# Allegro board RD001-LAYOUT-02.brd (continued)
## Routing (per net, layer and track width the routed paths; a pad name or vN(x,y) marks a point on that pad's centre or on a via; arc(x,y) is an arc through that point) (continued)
HS1_1: length 7.1
  TOP w0.5: v4(173.6,121) 176.8,117.8 176.8,115.53
  TOP w0.72: 176.8,115.53 R224.2
HS1_2: length 6.4
  TOP w0.5: 84.43,121 v4(90.5,121)
  TOP w0.72: R225.2 84.43,121
LGND: length 151.7
  TOP w0.3: v2(230.1,61.55) 229.87,61.22 229.66,60.86 ; v2(244.3,6.5) 244.66,6.5 R208.1 ; 240.04,9.49 240.04,8.71 v2(240,8.3) ; v2(240,3.5) 240.04,3.91 240.04,4.71 ; v2(244.3,9.3) 244.71,9.3 245.14,9 ; R55.1 259.9,10 260.05,9.85 v2(260.05,8.9) ; R70.1 247.7,10.96 v2(247.7,12.1)
  TOP w0.45: 226.95,95.01 226.95,93.09 ; 226.95,92.01 226.95,90.9 v2(228.3,89.55) v2(229.55,89.55) ; v2(229.8,99) 228.97,98.17 C61.1 227.35,97.4 226.95,97 226.95,96.31
  TOP w0.5: 256.04,16.09 256.04,17.41 ; 256.04,8.29 256.04,9.61 ; v2(257,11.2) 257,11.6 256.7,11.9 256.16,11.9 ; v2(235.3,96.55) 235.3,97.1 235.53,97.33 IC6.3 ; 256.04,12.19 256.04,13.61 ; 256.04,14.19 256.04,15.51 ; 256.04,6.39 256.04,7.71 ; 259.31,6.1 259.78,5.82 v2(260.2,5.4) ; v2(256.04,18.65) 256.04,17.99 ; 256.04,10.19 256.04,11.61
  TOP w0.55: 229.66,60.16 229.66,60.86
  TOP w0.72: 256.04,10.19 R51.1 256.04,9.61 ; R180.1 256.04,12.19 ; R180.1 256.16,11.9 ; R180.1 256.04,11.61 ; R197.2 240.04,4.71 ; 256.04,8.29 R53.1 256.04,7.71 ; 256.04,16.09 R181.1 256.04,15.51 ; 245.14,9 R209.1 ; R184.1 259.31,6.1 ; 256.04,17.99 R50.1 256.04,17.41 ; R196.2 240.04,9.49 ; 256.04,14.19 R52.1 256.04,13.61 ; R182.1 256.04,6.39
  TOP w0.92: 226.95,96.31 C88.1 226.95,95.01 ; 226.95,92.01 C89.1 226.95,93.09
  TOP w1: C3.1 292.5,121.5 ; C3.1 291,120 ; C3.1 294,120 ; C5.1 301.5,88.5 ; C5.1 303,90 ; C5.1 301.5,91.5 ; C4.1 301.5,105 ; C4.1 301.5,102 ; C4.1 303,103.5 ; C6.1 268,120 ; C6.1 266.5,121.5 ; C6.1 265,120 ; C2.1 278,120 ; C2.1 279.5,121.5 ; C2.1 281,120
  CONDUCTIVE4 w0.2: v2(237.4,14.1) 237.4,13.7 241.8,9.3 v2(242.8,9.3)
  BOTTOM w0.3: 226.65,42.05 v2(226.65,42.7) ; v2(237.4,14.1) 237.6,14.3 237.6,14.7 231.9,20.4 229,20.4 227.95,19.35 227.04,19.35 ; R22.1 245.24,61.36 v2(245.25,60.95) ; v2(260.2,5.4) 259.25,5.4 ; v2(246.4,17.2) 246.6,17 246.6,16.6 ; R66.1 v2(244.3,9.3) ; v2(240,3.5) 240,2.96 240.04,2.42 ; R45.1 v2(261,16.2) ; v2(260.05,8.9) 260.05,8.35 259.9,8.2 259.36,8.2 ; R25.1 225.26,44.94 v2(225.65,44.8) ; IC10.24 249.34,16.62 v2(249.3,17) ; 257.45,14.44 257.99,14.5 v2(258.4,14.5) 259.06,14.5 R43.1 ; 240.04,7.22 240,7.76 v2(240,8.3) ; v2(247.7,17.2) 247.7,16.45 ; 246.78,16.43 247.53,16.43 ; v2(247.7,12.1) 247.7,11.35 ; v2(230.1,61.55) 230.3,61.75 230.92,61.75 ; v2(257,11.2) 257.52,11.72 257.52,11.99 ; 253.62,17.3 v2(252.9,17.3) ; R64.1 v2(244.3,6.5)
  BOTTOM w0.45: 247.7,16.45 C24.1 247.53,16.43 ; D26.A 228.2,93.75 v2(228.25,93.8) ; 253.68,17.3 253.62,17.3 ; v2(221.6,25.45) R9.1 ; 247.7,11.35 247.7,11.32 ; C100.1 v2(269.5,27.3) 269.51,27.32 269.51,28.27 ; 257.52,12 257.52,11.99 ; 268.11,28.55 268.11,27.31 v2(268.1,27.3) ; 246.78,16.43 C23.1 246.6,16.6
  BOTTOM w0.5: v1(235.1,114.6) 233.6,114.6 233.15,114.15 D27.A ; R21.1 237.59,96.55 v2(235.3,96.55) ; R19.1 235.3,107.64 v1(235.3,106) ; v2(253.7,5.1) 253.7,5.77
  BOTTOM w0.55: D29.A 226.65,42.05 ; IC8.3 269.51,28.27 ; D28.A 230.92,61.75
  BOTTOM w0.72: 253.7,5.77 R54.1 ; 240.04,2.42 R195.2 ; 257.45,14.44 R48.1 ; 240.04,7.22 R194.2 ; 259.36,8.2 R56.1 ; 259.25,5.4 R61.1
  BOTTOM w0.825: IC8.4 268.11,28.55
  BOTTOM w0.92: R185.1 227.04,19.35
  BOTTOM w1: C5.1 303,90 ; C5.1 301.5,88.5 ; C5.1 301.5,91.5 ; C6.1 265,120 ; C6.1 266.5,121.5 ; C6.1 269.5,120 ; C2.1 279.5,121.5 ; C2.1 276.5,120 ; C2.1 281,120 ; C4.1 301.5,105 ; C4.1 301.5,102 ; C4.1 303,103.5 ; C3.1 294,120 ; C3.1 291,120 ; C3.1 292.5,121.5
  vias: v1(227.85,81.85) v1(227.85,79.75) v1(229.95,81.85) v1(229.95,79.75) v1(229.95,77.65) v1(235.05,120.5) v1(235.1,49.45) v1(235.1,46.05) v1(235.3,103.9) v1(235.3,101.8) v1(235.3,59.35) v1(235.3,57.25) v1(235.3,55.15) v1(235.4,73.8) v1(235.4,71.7) v1(235.4,68.7) v1(236.25,122.6) v1(236.35,51.15) v1(236.35,47.75) v1(236.35,44.35) v1(236.7,60.95) v1(237.15,120.5) v1(237.2,114.6) v1(237.4,106) v1(237.4,103.9) v1(237.4,101.8) v1(237.5,73.8) v1(237.5,71.7) v1(237.5,68.7) v1(238.35,122.6) v1(238.8,60.95) v1(239.3,120.5) v1(239.5,108.1) v1(239.5,106) v1(239.5,103.9) v1(239.5,101.8) v1(239.6,73.8) v1(239.6,71.7) v1(240.45,122.6) v1(240.9,60.95) v1(241.7,71.7) v1(242.55,122.6) v1(262,122.5) v1(271,122.5) v1(273,122.5) v1(273,120.5) v1(275,122.5) v1(275.1,28.6) v1(275.1,25.6) v1(275.1,22.6) v1(275.1,19.6) v1(275.1,16.6) v1(275.1,13.6) v1(275.1,10.6) v1(275.1,7.6) v1(277.1,27.1) v1(277.1,24.1) v1(277.1,21.1) v1(277.1,18.1) v1(277.1,15.1) v1(277.1,12.1) v1(277.1,9.1) v1(279.1,34.4) v1(279.1,31.4) v1(279.1,13.6) v1(279.1,10.6) v1(279.1,7.6) v1(281.1,32.9) v1(281.1,29.9) v1(281.1,12.1) v1(281.1,9.1) v1(283.1,34.4) v1(283.1,31.4) v1(283.1,13.6) v1(283.1,10.6) v1(283.1,7.6) v1(284,122.5) v1(285.1,32.9) v1(285.1,29.9) v1(285.1,12.1) v1(285.1,9.1) v1(286,122.5) v1(286,120.5) v1(287.1,34.4) v1(287.1,31.4) v1(287.1,28.4) v1(287.1,13.6) v1(287.1,10.6) v1(287.1,7.6) v1(288,122.5) v1(289.1,32.9) v1(289.1,29.9) v1(289.1,12.1) v1(289.1,9.1) v1(291.1,31.4) v1(291.1,28.4) v1(291.1,13.6) v1(291.1,10.6) v1(291.1,7.6) v1(293.1,32.9) v1(293.1,29.9) v1(293.1,12.1) v1(293.1,9.1) v1(295.1,34.4) v1(295.1,31.4) v1(295.1,28.4) v1(295.1,13.6) v1(295.1,10.6) v1(295.1,7.6) v1(297.1,32.9) v1(297.1,29.9) v1(297.1,12.1) v1(297.1,9.1) v1(297.5,122.5) v1(299,116.4) v1(299.1,34.4) v1(299.1,31.4) v1(299.1,13.6) v1(299.6,113.12) v1(299.9,110.8) v1(299.9,83.5) v1(299.9,81.5) v1(301.1,32.9) v1(301.1,29.9) v1(301.1,26.9) v1(301.1,23.9) v1(301.1,20.9) v1(301.1,17.9) v1(301.1,14.9) v1(301.92,116.4) v1(302,110) v1(302,96.5) v1(302,83.5) v1(302,81.5) v1(303.1,31.4) v1(303.1,28.4) v1(303.1,25.4) v1(303.1,22.4) v1(303.1,19.4) v1(303.1,16.4) v1(304,110) v1(304,108) v1(304,98.5) v1(304,96.5) v1(304,94.5) v1(304,85.5) v1(304,83.5) v1(304,81.5) v2(233.35,52.8) v2(234.6,52.8) v2(304.5,72) v2(304.5,66.6) v2(304.5,62) v2(304.5,57) v2(304.5,52) v2(304.5,47) v2(304.5,43.8) v2(304.5,40.55) v3(281.5,24.5) v3(281.5,18) v3(297.5,24.5)
OUTA1: length 162.8
  TOP w0.3: v2(140.6,107.5) 141.06,107.5 R111.1
  CONDUCTIVE3 w0.2: v2(217.7,6.1) 217,6.8 217,7.85 215.8,9.05 213,9.05 210.25,11.8 199.6,11.8 194.11,17.29 191.61,17.29 178.55,30.35 178.55,53.15 168.68,63.02 156.75,63.02 154.57,65.2 154.57,69.4 150.57,73.4 143.65,73.4 139,78.05 139,89.25 142.65,92.9 142.65,106.55 141.7,107.5 v2(140.6,107.5)
  BOTTOM w0.3: 220.03,6.88 220.03,6.36 220.06,5.82 ; v2(217.7,6.1) 217.7,5.75 218.1,5.35 219.36,5.35 219.84,5.6
  BOTTOM w0.6: IC21.4 220.03,6.88
  BOTTOM w0.72: 219.84,5.6 R187.2 220.06,5.82
OUTA2: length 12.9
  BOTTOM w0.3: 240.26,9.6 240.9,9.6 241.45,10.15 241.45,12.65 243.57,14.78 248.58,14.78
  BOTTOM w0.4: 248.58,14.78 IC10.22
  BOTTOM w0.72: R149.2 240.26,9.6
OUTB1: length 163.2
  TOP w0.3: v2(140.6,104.1) 141.01,104.1 141.5,103.9
  TOP w0.72: 141.5,103.9 R110.1
  CONDUCTIVE3 w0.2: v2(140.6,104.1) 141.65,104.1 142.25,103.5 142.25,93.1 138.6,89.45 138.6,77.88 143.48,73 150.4,73 154.18,69.22 154.18,65.03 156.57,62.62 168.47,62.62 178.15,52.95 178.15,30.15 191.41,16.89 193.91,16.89 199.4,11.4 210.05,11.4 212.95,8.5 215.75,8.5 216.6,7.65 216.6,3.15 v2(217.7,2.05)
  BOTTOM w0.3: 219.84,1.4 219.36,1.15 218.35,1.15 217.84,1.66 v2(217.7,2.05) ; 220.06,1.62 220.03,2.16 220.03,2.67
  BOTTOM w0.6: IC22.4 220.03,2.67
  BOTTOM w0.72: 219.84,1.4 R189.2 220.06,1.62
OUTB2: length 17.1
  BOTTOM w0.3: 240.26,4.8 241.2,4.8 242.05,5.65 242.05,12.4 243.78,14.12 248.58,14.12
  BOTTOM w0.4: IC10.21 248.58,14.12
  BOTTOM w0.72: 240.26,4.8 R150.2
OUTC1: length 102.2
  TOP w0.3: v2(163.38,60.25) 162.9,59.77 159.06,59.77 157.83,58.55 156.61,58.55 R113.1 ; 220.14,9.7 218.2,9.7 v2(215.9,7.4) ; R191.2 219.94,9.28 219.94,8.55
  TOP w0.6: 219.94,8.55 IC23.4
  TOP w0.72: 220.14,9.7 R191.2
  CONDUCTIVE3 w0.2: v2(215.9,7.4) 213.45,7.4 209.85,11 199.2,11 193.71,16.49 191.21,16.49 177.75,29.95 177.75,50.8 168.7,59.85 163.78,59.85 v2(163.38,60.25)
OUTC2: length 18.6
  TOP w0.3: 240.26,7 240.7,7 241.2,7.5 241.2,12.5 242.5,13.8 250.8,13.8 v2(251,14)
  TOP w0.72: 240.26,7 R151.2
  BOTTOM w0.3: v2(251,14) 250.67,13.75 250.4,13.47 249.93,13.47
  BOTTOM w0.4: IC10.20 249.93,13.47
OUTD1: length 102.3
  TOP w0.3: 220.29,5.5 219.4,5.5 219.25,5.35 v2(215.9,5.35) ; v2(162.88,61.4) 162.88,60.83 162.43,60.38 158.81,60.38 157.79,59.36 157.42,59.36 ; R193.2 219.94,5.08 219.94,4.35
  TOP w0.6: 219.94,4.35 IC24.4
  TOP w0.72: R193.2 220.29,5.5 ; 157.42,59.36 R112.1
  CONDUCTIVE3 w0.2: v2(215.9,5.35) 214.9,5.35 209.65,10.6 199,10.6 193.51,16.09 191.01,16.09 177.35,29.75 177.35,50.45 168.35,59.45 163.24,59.45 162.72,59.98 162.72,60.84 162.88,61 v2(162.88,61.4)
OUTD2: length 22.4
  TOP w0.3: 240.26,2.2 240.75,2.2 242.05,3.5 242.05,12.45 242.6,13 v2(251,13)
  TOP w0.72: R152.2 240.26,2.2
  BOTTOM w0.3: v2(251,13) 250.63,12.82 249.97,12.82
  BOTTOM w0.4: IC10.19 249.97,12.82
OUTE: length 129.2
  TOP w0.3: 230.94,59.34 230.94,58.74 231.08,58.6 v2(231.7,58.6) ; v2(232.1,43.75) 232.1,40.6 231.5,40 230.2,40 ; 234.8,92.65 234.8,94.75 v2(235.25,95.2) 235.38,95.59 235.67,95.88 236.03,96.06
  TOP w0.55: 230.94,59.34 IC7.2 ; IC6.2 236.03,96.06
  TOP w2.1: 230.2,40 TP25.1 ; 234.8,92.65 TP23.1
  CONDUCTIVE4 w0.2: v2(251,12) 247.9,15.1 242.9,15.1 239.6,18.4 232.05,18.4 225.65,24.8 225.65,37.8 231.6,43.75 v2(232.1,43.75) 232.8,44.45 232.8,45.3 230.75,47.35 230.75,57.65 v2(231.7,58.6) 231.05,59.25 229.45,59.25 228.25,60.45 228.25,76.1 225.25,79.1 225.25,80.55 235.25,90.55 v2(235.25,95.2)
  BOTTOM w0.3: 250.01,12.18 250.63,12.18 v2(251,12)
  BOTTOM w0.4: IC10.18 250.01,12.18
OUTF: length 141.5
  TOP w0.3: 236.16,98.74 235.14,98.74 234.2,97.8 v2(234.2,95.9) ; 230.2,44.7 231.68,45 v2(232.1,45) ; v2(229.3,58.6) 228.56,58.6 228.26,58.9 228.26,59.52 ; v2(222.6,97.6) 222.6,99.4 222.1,99.9 220.8,99.9
  TOP w0.825: 228.26,59.52 IC7.4 ; IC6.4 236.16,98.74
  TOP w2.1: 230.2,44.7 TP26.1 ; 220.8,99.9 TP24.1
  CONDUCTIVE4 w0.2: v2(251,10.75) 247.05,14.7 242.7,14.7 239.4,18 231.85,18 225.25,24.6 225.25,38 231.25,44 231.25,44.15 v2(232.1,45) 232.1,45.4 230.35,47.15 230.35,57.55 v2(229.3,58.6) 227.85,60.05 227.85,75.9 224.85,78.9 224.85,80.75 234.2,90.1 v2(234.2,95.9) 233.74,95.75 231.95,95.75 230.1,97.6 v2(222.6,97.6)
  BOTTOM w0.3: v2(251,10.75) 250.81,11.12 250.4,11.53 249.93,11.53
  BOTTOM w0.4: IC10.17 249.93,11.53
PFC_OUT: length 289.9
  TOP w1: v2(186,6.25) 184.65,4.9 184.65,4.88 184.1,3.4
  TOP w2.1: 184.1,3.4 TP44.1
  CONDUCTIVE4 w5: C7.2 139.1,27.4 133.8,32.7 121.22,32.7 101.3,52.62 101.3,71.68 98.95,74.03 98.95,112.6 99.7,113.35
  BOTTOM w0: C1.2 178.9,21.4 179.8,20.5 R178.2
  BOTTOM w0.3: 172.14,14.72 172.14,17.24 175,20.1 C1.2
  BOTTOM w0.5: 189,20.68 189,14.45 185.25,10.7 185.25,7 v2(186,6.25)
  BOTTOM w0.72: R92.2 172.14,14.72
  BOTTOM w3: 162.15,28.6 162.15,31.4 ; 162.15,28.6 159.35,28.6 ; 162.15,28.6 164.95,28.6 ; 162.15,31.4 161.5,32.05 161.5,45.52 166.38,50.4 D2.C 166.38,54.7 ; 162.15,31.4 159.35,28.6 ; 162.15,31.4 164.95,28.6 ; 159.35,28.6 156,28.6 148.8,21.4 C7.2 136.2,24.3 136.2,45.85 135.18,46.87 D1.C 135.18,54.7 ; T4.2 189,21.35 ; 189,21.35 189,20.68 ; 189,21.35 177.25,21.35 C1.2 177.2,23.33 171.93,28.6 164.95,28.6
PFC_VIN: length 8.8
  TOP w0.5: D9.C 124.58,117.05 v2(125.05,117.05) v2(126.3,117.05)
  TOP w1: D9.C D8.C
  BOTTOM w0.5: v2(126.3,117.05) v2(125.05,117.05) 124.61,117.05 R95.2
PN: length 393.4
  TOP w0.3: R191.1 221.64,9.22 222.06,8.8 IC23.3 ; v2(218.7,4.6) 218.6,4.24 218.6,3.9 ; v2(161.6,5.2) 161.1,5.7 R176.1 ; 227.75,4.89 227.8,5.49 v2(227.8,5.9) 227.12,5.9 226.9,5.67 226.47,5.67 ; 158.83,62.52 158.83,62.12 159.12,61.83 161.19,61.83 ; 161.37,62 161.19,61.83 ; 161.37,62 161.37,61.83 ; 161.37,62 161.37,62.52 ; 161.19,61.83 161.37,61.83 ; 218.6,8 v2(218.6,8.9) ; 88.8,73.53 v2(88.8,72.8) ; Q4.S 159.9,76.55 161.25,75.2 163.25,75.2 164.05,74.4 164.05,73.94 ; 161.37,61.83 161.7,61.49 v2(161.82,61.1) ; 164.24,73.25 170.51,73.25 R33.1 ; R175.1 155.21,6.5 v2(154.8,6.45) ; v2(225.5,1.95) 225.5,1.27 225.7,1.07 226.12,1.07 ; 221.76,9.7 222.19,10 v2(222.6,10) ; v2(224.7,10.05) 226.95,10.05 227,10 227.41,9.57 ; R71.1 v2(155.7,42.9) ; 126.58,49.1 v2(127.8,49.1)
  TOP w0.4: v2(152.4,13.1) 153.39,13.1 154.14,12.35 154.14,11.65 ; 202.4,15.72 v2(202.4,16.5) ; 85.2,73.89 v2(85.2,72.5)
  TOP w0.45: C35.1 151.2,41.3 150.9,41.6 v2(150.3,41.6) ; C62.1 v2(147.9,45.6) ; C57.1 153.04,65 153.04,66.99 v2(153.5,67.45) ; v2(144.7,43.8) 143.74,43.8 143.34,43.4 143.34,42.99 ; v2(167.3,39.2) 167.16,39.06 164.37,39.06 ; 226.47,5.67 C73.1 ; C97.1 218.6,8 ; 143.34,41.37 143.34,40.4 ; 143.34,40.4 C81.1 ; 143.34,40.4 C80.1 ; C70.1 88.8,73.53 ; 226.12,1.07 C74.1 ; 218.6,3.9 C98.1 ; v2(130.4,43.6) 133.18,43.6
  TOP w0.5: v2(172.64,91.2) 172.68,91.24 R223.1 ; 145.03,103.83 145.03,100 ; 145.03,103.83 IC5.5 ; 145.03,103.83 145.03,106.1 145.3,106.37 IC5.3 ; R225.1 82.86,121.92 v2(82.87,121.93) ; v2(150.3,41.6) 149.57,41.6 ; v2(140.6,105.1) 140.8,105.3 C53.1 ; v2(120.4,44.8) 120.4,42.66 119.2,41.46 117.59,41.46 ; 221.76,5.5 222.3,5.5 v2(222.6,5.2) 222.6,4.68 IC24.3 ; v2(150.3,43.9) 149.57,43.9 ; v2(176.8,113.07) R224.1 ; 129.68,62.56 130.84,62.56 v2(130.9,62.5) ; C54.1 v2(140.6,108.7) ; 154.14,11.11 154.14,9.79
  TOP w0.55: IC4.3 158.83,62.52 ; 143.34,42.99 143.34,41.37 ; 164.05,73.94 D25.A 164.24,73.25 ; IC4.5 161.37,62.52
  TOP w0.7: D50.C 85.2,73.89
  TOP w0.72: 164.37,39.06 R221.1 ; 154.14,11.11 R174.1 154.14,11.65 ; R73.1 126.58,49.1 ; 154.14,9.79 R198.1 ; R220.1 129.68,62.56 ; 117.59,41.46 R222.1 ; 221.76,9.7 R191.1 ; 221.76,5.5 R193.1
  TOP w0.8: 227.75,4.89 IC16.4 ; 227.41,9.57 IC15.4
  TOP w0.92: 149.57,41.6 C83.1 ; 149.57,43.9 C82.1
  CONDUCTIVE3 w0.2: v2(105.6,76.9) 106.7,75.8 121.4,75.8 122.75,74.45 122.75,58.5 124.6,56.65 124.6,45.3 132.28,37.62 149.05,37.62 152.6,34.08 152.6,20.6 158.9,14.3 158.9,3.74 v2(158.7,3.3) ; v2(161.6,3.95) 162.7,5.05 162.7,15.63 156.2,22.13 156.2,32.4 149.2,39.4 142.3,39.4 131.9,49.8 128.8,49.8 126.45,52.15 126.45,73.94 v2(126.6,74.4)
  BOTTOM w0.3: C48.1 146.08,9.29 144.7,9.29 ; 157.86,3 158.29,3.3 v2(158.7,3.3) 159.47,2.52 C76.1 ; 160.64,7.04 160.64,5.96 ; 161.99,61.88 161.99,61.34 v2(161.82,61.1) ; 151,7.83 151.47,7.83 v2(151.8,7.5) ; 148.56,7.42 148.9,7.42 149.3,7.83 ; 160.64,7.43 160.64,8.15 C38.1 ; 147.08,3.24 146.46,3.24 v2(146.3,3.4) ; 159.48,11.82 160.15,11.82 160.64,12.32 160.64,14.48 161,14.84 R90.1 ; 149.92,7.83 149.3,7.83 ; 149.3,7.83 148.75,8.38 148.41,8.38 ; 150.56,2.12 150.3,2.59 v2(150.3,3.2) 151.03,3.2 ; C36.1 105.08,76.38 v2(105.6,76.9) 105.12,77.38 103.81,77.38 103.54,77.65 103.54,78.32 ; R8.1 125.2,77.7 125.6,77.3 125.6,75.4 v2(126.6,74.4) 126.08,73.88 C34.1 ; v2(227.8,5.9) 227.75,6.31 IC13.4 ; 147.42,3.24 147.96,3.2 148.3,3.2 ; 148.4,4.11 148.4,3.7 148.47,3.38 ; v2(157.6,9.8) 157.6,10.7 158.72,11.82 159.3,11.82 ; C47.1 148.34,7.42 147.58,8.18 146.98,8.75 ; 157.64,2.84 157.64,1.76
  BOTTOM w0.4: 151,7.83 IC3.16 149.92,7.83 ; 157.45,13.94 158.38,13.94 158.5,13.82 ; R93.1 152.4,13.91 v2(152.4,13.1) 152.81,13.14 C40.1
  BOTTOM w0.45: 160.72,4.5 161.28,3.95 v2(161.6,3.95) ; 148.41,8.38 C49.1 ; 148.56,7.42 C47.1 ; C71.1 224.75,10.1 v2(224.7,10.05) ; C72.1 v2(224.7,5.6) ; C45.1 151.03,3.2 ; 148.47,3.38 C43.1 148.3,3.2 ; C42.1 148.4,4.11 ; C96.1 v2(218.7,2.05) ; 159.48,11.82 159.3,11.82 ; C95.1 v2(218.7,6.1)
  BOTTOM w0.5: v2(225.5,1.95) 226.67,1.95 227.2,2.23 ; 165.99,117.3 166.3,117.3 ; 165.99,117.3 159.26,117.3 R29.1 ; 165.99,117.3 166.3,117.61 ; 166.3,117.3 166.3,117.61 ; 166.3,117.3 166.61,117.3 ; R101.1 161.13,5.57 161.5,5.2 v2(161.6,5.2) 162.34,5.2 R2.1 ; 166.3,117.61 166.61,117.3 ; 166.3,117.61 Q6.S ; 166.61,117.3 168.4,117.3 169.05,116.65 D22.A ; 157.2,14.23 157.2,15.65 156.45,16.4 154.05,16.4 v2(153.9,16.25) ; 151.59,13.14 152.36,13.14 v2(152.4,13.1) ; 221.63,1.4 222.4,1.4 v2(222.95,1.95) 222.95,2.15 222.35,2.75 IC22.3 ; 151.01,13.14 149.69,13.14 ; R187.1 221.74,5.2 v2(222.6,5.2) 222.6,6.62 IC21.3
  BOTTOM w0.72: 221.63,1.4 R189.1 ; 160.64,7.43 R102.1 160.64,7.04 ; 147.42,3.24 R98.1 147.08,3.24 ; 157.64,1.76 R96.1 ; 157.2,14.23 R104.1 157.45,13.94 ; 150.56,2.12 R99.1 ; 151.01,13.14 R103.1 151.59,13.14 ; 149.69,13.14 R100.1 ; 157.64,2.84 C77.1 157.86,3 ; 161.99,61.88 C56.1 ; 160.64,5.96 R101.1
  BOTTOM w0.8: 227.2,2.23 IC14.4
  BOTTOM w0.895: 103.54,78.32 R7.1
  BOTTOM w1.1: 146.98,8.75 C48.1
  BOTTOM w1.2: 144.7,9.29 D49.A
  BOTTOM w1.4: TP45.1 178,2.1 R179.1
  vias: v2(125.15,41.1) v2(126.4,41.1) v2(141.1,101) v2(141.1,99.7) v2(141.1,98.4) v2(142.75,90.05) v2(142.75,88.8) v2(155.9,104.1) v2(155.9,102.8) v2(164.18,61.27) v2(166.1,61.85) v2(166.1,60.6) v2(203.7,12.55) v2(204.95,12.55) v2(210.85,6) v2(210.85,4.75) v2(212.1,6) v2(212.1,4.75)
SIG1: length 95.4
  BOTTOM w0: L11.2 51.9,32.2
  BOTTOM w0.8: R79.2 55.74,27.56 L11.2
  BOTTOM w1.5: C78.2 F1.2
  BOTTOM w5: F1.2 49.5,41.24 44.75,36.49 44.75,22.2 RV1.1 44.2,22.2 C30.2 39.5,14.2 42.2,11.5 45,11.5 51.9,18.4 51.9,32.2
SIG2: length 77.9
  BOTTOM w0.15: C79.2 37,5 C30.1
  BOTTOM w0.8: L11.3 55.74,12.84 R80.1
  BOTTOM w5: 49.8,5.6 48.2,4 32.95,4 C79.2 31.95,20.8 35.95,24.8 ; CN1.3 24.8,26.2 34.6,26.2
SIG6: length 246.3
  TOP w0.15: C65.1 73.3,87.75 ; L12.4 111.95,8.2 C63.2 ; 117.9,94.5 L2.1
  TOP w1: 117.2,121.2 121.08,117.33 D9.A
  TOP w5: 109.05,9.75 111.9,12.6 ; 109.05,9.75 111.9,9.75 111.9,12.6 ; 109.05,9.75 L12.4 ; 111.9,12.6 111.9,26.8 114.15,29.05 114.15,35.26 109.85,39.56 109.85,46.47 99.25,57.07 99.25,72.5 88.34,83.41 77.64,83.41 73.3,87.75 ; 117.9,94.5 117.9,106.5 112.4,112 81.75,112 C33.1
  BOTTOM w0.15: 73.66,87.63 73.3,87.99 C65.1 ; L2.1 117.9,94.5
  BOTTOM w5: C33.1 69.3,109.85 69.3,92.75 C65.1 ; 117.2,121.2 117.2,109.9 117.9,109.2 117.9,94.5
SIG8: length 121.5
  TOP w1: D8.A 119.28,112.9 113.38,118.8 112.1,118.8 109.7,121.2
  TOP w5: C33.2 89.05,94.65 L1.1 ; C65.2 73.3,62.3 76.1,59.5 84.4,59.5 86.45,57.45 86.45,56.3
  BOTTOM w5: L1.1 97.6,94.5 109.3,106.2 109.3,121.2 ; 77.6,95.65 80.8,92.45 80.8,83 73.3,75.5 C65.2
SIG9: length 4.6
  BOTTOM w0.5: IC1.2 60.47,24.2 R79.1 61.73,24.2 IC1.3
SIG10: length 4.6
  BOTTOM w0.5: IC1.6 61.73,16.2 R80.2 60.47,16.2 IC1.7
SIG11: length 50.3
  BOTTOM w3: 142.1,68.38 144.31,68.38 152.89,59.79 156.01,59.79 161.3,54.5 D2.A
  BOTTOM w5: 141.7,69.97 141.7,70.98 135.57,77.11 135.57,91.17 136.55,92.15
SIG12: length 40.7
  BOTTOM w0.15: 110.2,94.5 L1.2
  BOTTOM w3: 127.8,57 126.2,58.6 126.2,63.55 121.3,68.45
  BOTTOM w5: 119.2,72.7 113.28,78.62 113.28,87.58 110.2,90.65 110.2,94.5
SIG15: length 9.9
  BOTTOM w0.3: 129.26,74.8 129.61,74.39 T2.1 ; 129.04,75.02 129,75.56 129,76.28
  BOTTOM w0.55: D12.A 129,76.28
  BOTTOM w0.72: 129.04,75.02 R81.2 129.26,74.8
SIG16: length 1.8
  BOTTOM w0.3: 127.76,74.74 127.76,73.96 127.4,73.6 127.06,73.6
  BOTTOM w0.45: 127.06,73.6 C34.2
  BOTTOM w0.72: R81.1 127.76,74.74
SIG18: length 12.7
  BOTTOM w0: T2.3 142.37,62.45 142.45,62.45
  BOTTOM w3: 142.1,63.23 142.45,62.88 142.45,62.45 148.25,56.65 Q2.D
SIG20: length 10.7
  BOTTOM w0.3: R85.2 108.9,74.8 111.1,72.6 T3.1 ; 108.04,75.02 108,75.56 108,77.78
  BOTTOM w0.55: D13.A 108,77.78
  BOTTOM w0.72: 108.04,75.02 R85.2
SIG21: length 2
  BOTTOM w0.3: R85.1 106.22,74.8 105.92,75.1 105.92,75.92
  BOTTOM w0.45: C36.2 105.92,75.92
SIG23: length 6.4
  TOP w0.3: 160.47,44.83 159.59,44.8 158.9,44.8 ; 158.65,44.41 158.65,43.61 R71.2 ; 158.65,46.46 158.65,45.19
  TOP w0.92: R108.2 158.65,44.41 ; R108.2 158.65,45.19 ; R108.2 158.9,44.8 ; R72.2 158.65,46.46
  TOP w1.17: 160.47,44.83 FB1.1
SIG24: length 4.5
  TOP w0.3: 151.38,39.98 151.64,39.76 152.5,39.76 ; 153.74,39.76 152.66,39.76 ; 153.93,38.19 153.93,39 153.9,39.54
  TOP w0.45: 151.38,39.98 C35.2
  TOP w0.55: D31.A 153.93,38.19
  TOP w0.72: 153.74,39.76 R172.2 153.9,39.54 ; 152.66,39.76 R82.2 152.5,39.76
SIG25: length 4.4
  TOP w0.3: 133.57,42.09 133.57,42.6 134.03,43.05 134.03,43.49 ; 135.16,43.77 135.1,44.31 135.1,44.85 ; 134.2,43.6 135.08,43.6
  TOP w0.45: 134.2,43.6 C37.2 134.03,43.49
  TOP w0.55: 133.57,42.09 D33.A
  TOP w0.72: 135.16,43.77 R173.2 135.08,43.6 ; R86.2 135.1,44.85
SIG27: length 6.4
  TOP w0.3: 122.75,44.83 123.62,44.9 124.31,44.9 ; 124.45,47.7 124.45,48.39 R73.2 ; 124.45,46.56 124.45,45.29
  TOP w0.92: 124.45,46.56 R109.2 124.45,47.7 ; 124.45,45.29 R74.2 124.31,44.9
  TOP w1.17: 122.75,44.83 FB2.1
SIG30: length 16.2
  TOP w0.3: 137.91,45.62 136.78,45.62 136.16,46.24 135.32,46.24 ; R86.1 134.14,47.2 131.33,47.2 ; 138.29,45.62 141.82,45.62 142.06,45.87 142.06,46.44 ; D38.A 131.62,45.48 130.68,46.42 D39.C
  TOP w0.55: 138.29,45.62 D32.C 137.91,45.62 ; IC2.7 142.06,46.44
  TOP w0.72: 135.32,46.24 R86.1
  TOP w1.1: 131.33,47.2 D39.C
SIG39: length 6.8
  BOTTOM w0.3: R89.2 163,13.34 164.16,14.5 168.14,14.5
  BOTTOM w0.72: R91.1 168.14,14.5
SIG40: length 1.2
  BOTTOM w0.3: 170.79,14.5 169.71,14.5
  BOTTOM w0.72: R92.1 170.79,14.5 ; 169.71,14.5 R91.2
SIG43: length 3.5
  BOTTOM w0.3: C45.2 151.95,3.23 152.82,3.23 ; 151.93,3.38 151.93,4 151.45,4.47 150.91,4.47
  BOTTOM w0.45: 151.93,3.38 C45.2 ; C46.2 152.82,3.23
  BOTTOM w0.6: IC3.11 150.91,4.47
SIG44: length 1.4
  BOTTOM w0.3: C46.1 152.53,1.9 151.99,1.9
  BOTTOM w0.72: 151.99,1.9 R99.2
SIG45: length 4.1
  BOTTOM w0.3: 149.32,3.02 149.32,2.27 ; 149.94,5.22 149.62,5.22 149.32,4.92 149.32,3.38
  BOTTOM w0.4: IC3.12 149.94,5.22
  BOTTOM w0.45: 149.32,2.27 149.32,2.1 ; 149.32,3.38 149.32,3.02
SIG46: length 1.2
  BOTTOM w0.3: 148.3,2.1 147.96,2.1 147.45,1.96
  BOTTOM w0.45: C44.1 148.3,2.1
  BOTTOM w0.72: 147.45,1.96 R98.2
SIG47: length 7.2
  BOTTOM w0.3: 155.3,12.96 154.87,12.52 154.21,11.86 153.41,11.86 ; 153.4,11.64 153.4,10.93 155.2,9.12 155.75,9.12
  BOTTOM w0.4: 156.32,9.12 155.75,9.12
  BOTTOM w0.72: 153.41,11.86 C40.2 153.4,11.64
  BOTTOM w0.83: 155.3,12.96 C41.2
SIG48: length 2.9
  BOTTOM w0.4: 154.77,14.8 154.15,14.8 153.31,15.64 152.77,15.64
  BOTTOM w0.72: 152.77,15.64 R93.2
  BOTTOM w0.83: C41.1 154.77,14.8
SIG49: length 23.9
  TOP w0.3: v2(154.8,8.5) 158.65,8.5 160.6,6.55 161.55,6.55 162.85,5.25 162.85,3.16 163.05,1.6
  TOP w2.1: 163.05,1.6 TP8.1
  BOTTOM w0.3: 161.37,11.06 160.4,11.06 160.31,10.97 159.45,10.97 ; v2(154.8,8.5) 155.21,8.47 155.63,8.47 ; 156.85,8.47 157.38,8.47 159.3,10.4 159.3,10.8 ; 161.72,11.06 162.88,11.06
  BOTTOM w0.4: 155.63,8.47 156.85,8.47
  BOTTOM w0.45: 159.3,10.8 C39.2 159.45,10.97
  BOTTOM w0.72: 161.72,11.06 R227.2 161.37,11.06 ; 162.88,11.06 R89.1
SIG50: length 2.1
  BOTTOM w0.3: 149.78,9.12 149.2,9.12 149.1,9.22 148.41,9.22
  BOTTOM w0.4: 149.78,9.12 IC3.18
  BOTTOM w0.45: 148.4,9.22 148.41,9.22
SIG51: length 5
  BOTTOM w0.3: 156.53,10.53 158.5,12.5 158.5,12.84 ; 158.59,12.97 159.22,12.97 R171.1
  BOTTOM w0.45: 158.59,12.97 C50.2 158.5,12.84
  BOTTOM w0.6: 156.32,10.53 156.53,10.53
SIG52: length 7.2
  TOP w0.3: 152.64,9.5 149.8,9.5 v2(149.2,10.1)
  TOP w0.72: R198.2 152.64,9.5
  BOTTOM w0.3: 149.85,9.78 149.43,9.78 149.2,10 v2(149.2,10.1) 149.2,11.2 149.4,11.7
  BOTTOM w0.4: IC3.19 149.85,9.78
  BOTTOM w0.72: R100.2 149.4,11.7
SIG53: length 4.6
  TOP w0.3: R176.2 158.76,6.2 v2(158.2,6.2)
  BOTTOM w0.3: R101.2 158.96,6.2 v2(158.2,6.2) 157.88,6.53 157.02,6.53
  BOTTOM w0.4: 156.32,6.53 157.02,6.53
SIG54: length 4.5
  TOP w0.3: R175.2 157.74,7.2 v2(158.2,7.2)
  BOTTOM w0.3: 157.02,7.17 157.79,7.17 v2(158.2,7.2) 159.15,7.2
  BOTTOM w0.4: 156.32,7.17 157.02,7.17
  BOTTOM w0.72: 159.15,7.2 R102.2
SIG55: length 4.1
  TOP w0.3: v2(151.8,10.6) 152.37,11.17 R174.2
  BOTTOM w0.3: 150.91,10.53 151.39,10.53 v2(151.8,10.6) 151.8,11.36 R103.2
  BOTTOM w0.6: IC3.20 150.91,10.53
SIG56: length 5.3
  BOTTOM w0.3: 157.2,12.59 157.2,12.15 156.55,11.5 155.74,11.5 155,10.76 155,10.2 155.43,9.78 155.65,9.78
  BOTTOM w0.4: 156.32,9.78 155.65,9.78
  BOTTOM w0.72: 157.2,12.59 R104.2
SIG60: length 1.2
  BOTTOM w0.5: 123.9,114.99 123.9,113.91
  BOTTOM w0.72: R95.1 123.9,114.99 ; 123.9,113.91 R94.2
SIG61: length 199
  CONDUCTIVE3 w1: v2(166.35,3.4) 166.35,2.25 165.3,1.2 144.5,1.2 113,32.7 113,45.35 103.7,54.65 103.7,72.2 85.45,90.45 85.45,102.45 94.1,111.1 v2(123.9,111.1)
  BOTTOM w0.3: 163.4,8.06 164.26,8.06 166.35,5.97 v2(166.35,3.4)
  BOTTOM w0.5: 123.9,112.37 v2(123.9,111.1)
  BOTTOM w0.72: R94.1 123.9,112.37 ; R1.2 163.4,8.06
SIG62: length 18.1
  TOP w0.3: v2(154.8,7.45) 154.25,7.45 154,7.2 154,5.7 154.7,5 155.75,5 157.8,2.95 TP7.1
  BOTTOM w0.3: 162.12,9.34 163.28,9.34 ; 160.48,9.34 161.77,9.34 ; 156.98,7.83 157.75,7.83 159.26,9.34 160.12,9.34 ; v2(154.8,7.45) 155.18,7.83 155.78,7.83
  BOTTOM w0.4: 155.78,7.83 156.98,7.83
  BOTTOM w0.45: 160.12,9.34 C38.2 160.48,9.34
  BOTTOM w0.72: 162.12,9.34 R228.2 161.77,9.34 ; 163.28,9.34 R1.1
SIG65: length 6.2
  TOP w0.3: v2(157.55,66.62) 157.56,67.04 157.56,67.62
  TOP w0.55: IC4.13 157.56,67.62
  BOTTOM w0.3: v2(157.55,66.62) 157.55,66.08 C19.2 157.97,65.15 158.15,64.97 159.2,64.97 159.58,65.35 160.27,65.8
  BOTTOM w1.1: 160.27,65.8 D17.C
SIG75: length 9.4
  TOP w0.3: 152.33,107.64 153.1,107.64 ; 153.1,107.64 153.3,107.64 ; 153.1,107.64 153.3,107.44 ; 153.1,107.64 153.3,107.84 ; 153.3,107.84 153.3,109.8 v2(151.95,111.15) ; 153.3,107.84 153.3,107.64 ; 153.3,107.64 153.3,107.44 ; 153.3,107.44 153.3,107
  TOP w0.45: 153.3,107 C18.2
  TOP w0.55: IC5.13 152.33,107.64
  BOTTOM w0.3: v2(151.95,111.15) 151.95,112.67
  BOTTOM w1.1: 151.95,112.67 D16.C
SIG82: length 22.4
  TOP w0.3: TP14.1 159.8,115.8 159.3,116.3 157.8,116.3 155.4,118.7 Q6.G
  BOTTOM w0.3: 160,115.3 159.31,115.36 158.82,115.36 ; 160.25,114.73 160.25,113.57 ; R29.2 157.8,115.36 155.4,117.76 Q6.G
  BOTTOM w0.72: R29.2 158.82,115.36
  BOTTOM w0.92: 160.25,113.57 R136.2 ; 160,115.3 R137.2 160.25,114.73
SIG86: length 17.1
  TOP w0.3: v2(136.7,2) 136.4,1.7 135.86,1.7
  TOP w0.72: 135.86,1.7 R120.2
  BOTTOM w0.3: 149.92,7.17 149.6,7.17 149,6.58 148.57,6.58 ; 146.5,6.05 145.56,6.05 144.7,6.31 ; 148.22,6.58 147.72,6.58 147.66,6.51 146.98,6.05 ; 144.1,6.31 141.01,6.31 v2(136.7,2)
  BOTTOM w0.4: IC3.15 149.92,7.17
  BOTTOM w0.45: 148.57,6.58 C47.2 148.22,6.58
  BOTTOM w1.1: 146.5,6.05 C48.2 146.98,6.05
  BOTTOM w1.2: 144.7,6.31 D49.C 144.1,6.31
SIG89: length 19.2
  TOP w0.3: R111.2 142.84,106.58 142.46,106.2 v2(140.6,106.2) ; 143.06,108.7 144.35,108.7 144.7,109.05 145.72,109.05 ; v2(135.4,111.6) TP38.1 ; 142.84,108.54 142.84,107.46
  TOP w0.72: 142.84,108.54 C54.2 143.06,108.7 ; 142.84,107.46 R111.2
  TOP w0.825: IC5.1 145.72,109.05
  CONDUCTIVE3 w0.2: v2(135.4,111.6) 138.1,111.6 139.9,109.8 139.9,106.9 v2(140.6,106.2)
SIG90: length 29.9
  TOP w0.3: 143.06,105.3 143.6,105.3 143.9,105.6 143.9,106.4 145.14,107.64 145.75,107.64 ; v2(140.6,102.8) 142.5,102.8 142.84,103.14 R110.2 ; v2(129.1,111.6) TP39.1 ; 142.84,105.14 142.84,104.06
  TOP w0.55: IC5.2 145.75,107.64
  TOP w0.72: 143.06,105.3 C53.2 142.84,105.14 ; 142.84,104.06 R110.2
  CONDUCTIVE3 w0.2: v2(140.6,102.8) 139.5,103.9 139.5,109.6 138.2,110.9 129.8,110.9 v2(129.1,111.6)
SIG91: length 11.7
  TOP w0.15: IC4.7 164.05,63.45
  TOP w0.45: 168.83,65.7 169.5,65.7 169.8,65.4 169.8,63.55 ; 164.05,63.45 164.57,62.92 C58.2 165.43,63.05 166.15,63.05 166.81,63.25 ; 171.43,63.14 170.9,63.25 170.2,63.25 ; 168.19,63.25 169.41,63.25
  TOP w0.72: 171.43,63.14 R122.2
  TOP w0.895: 168.83,65.7 R115.1
  TOP w0.92: C85.2 169.8,63.55 ; C85.2 169.41,63.25 ; C85.2 170.2,63.25 ; 166.81,63.25 C84.2 168.19,63.25
SIG92: length 4.5
  TOP w0.3: v2(165.1,63.88) 165.71,63.88 165.94,64.1 165.94,64.77
  TOP w0.895: 165.94,64.77 R115.2
  BOTTOM w0.3: 165.05,65.11 165.1,64.29 v2(165.1,63.88)
  BOTTOM w1.1: 165.05,65.11 D17.A
SIG93: length 8.1
  TOP w0.3: 154.7,61.84 154.7,61.08 155.14,60.64 R113.2 ; 155.8,60.86 156.15,61.27 156.15,62.42 ; 152.7,61 153.68,61.95 153.79,62.06 C57.2
  TOP w0.72: 155.8,60.86 R113.2 ; 154.7,61.84 C57.2
  TOP w0.825: IC4.1 156.15,62.42
  TOP w2.1: 152.7,61 TP9.1
SIG94: length 27.6
  TOP w0.3: 157.31,60.64 158.23,60.64 158.56,60.98 160.43,60.98 v2(160.78,61.1) ; 157.56,62.47 157.56,61.69 157.2,61.33 157.2,60.78 ; v2(152.8,68.15) 151.9,67.25 151.9,65.45 150.95,64.5 148.85,64.5
  TOP w0.55: IC4.2 157.56,62.47
  TOP w0.72: 157.31,60.64 R112.2 157.2,60.78
  TOP w2.1: 148.85,64.5 TP10.1
  CONDUCTIVE4 w0.2: v2(152.8,68.15) 152.8,66.13 155.85,63.08 159.45,63.08 160.78,61.75 v2(160.78,61.1)
  BOTTOM w0.3: v2(160.78,61.1) 160.71,61.16 160.71,61.88
  BOTTOM w0.72: 160.71,61.88 C56.2
SIG95: length 18.7
  TOP w0.3: v2(153.2,99.3) 152.1,98.2 151.21,98.2
  TOP w0.895: 151.21,98.2 R114.2
  BOTTOM w0.3: 156.45,112.67 156.4,111.84 156.4,107.75 152.45,103.8 152.45,100.05 v2(153.2,99.3)
  BOTTOM w1.1: 156.45,112.67 D16.A
SIG100: length 2.5
  TOP w0.3: 154.07,47.1 155.7,47.1
  TOP w0.92: 155.7,47.1 R72.1
  TOP w1.1: D36.C 154.07,47.1
SIG101: length 1.5
  TOP w0.3: 154.59,44.8 155.88,44.8
  TOP w0.8: D37.A 154.59,44.8
  TOP w0.92: 155.88,44.8 R108.1
SIG102: length 13.7
  TOP w0.3: R82.1 152.5,41.67 152.18,42 152.18,42.51 ; 151.24,47.1 150.66,47.26 144.98,47.26 ; 152.18,42.89 152.18,43.4 152.43,43.65 D37.C ; 151.47,46.9 151.47,45.42 151.53,45.37 152.05,44.8
  TOP w0.55: 152.18,42.51 152.18,42.89
  TOP w0.8: 151.24,47.1 D36.A 151.47,46.9
  TOP w0.825: IC2.5 144.98,47.26
  TOP w1.1: 152.05,44.8 D37.C
SIG104: length 10.2
  TOP w0.45: 146.55,44.29 146.3,44.86 146.3,44.88 146.07,45.1 C62.2 143.8,45.6 143.34,46.06 143.34,46.63 ; 146.55,43.24 146.55,41.99 ; 146.56,39.77 146.55,40.3 146.55,40.99
  TOP w0.55: 143.34,47.26 143.34,46.63
  TOP w0.72: 146.56,39.77 R121.2
  TOP w0.92: 146.55,41.99 C83.2 146.55,40.99 ; 146.55,44.29 C82.2 146.55,43.24
SIG105: length 1.5
  TOP w0.3: 128.51,47.2 127.22,47.2
  TOP w0.8: D39.A 128.51,47.2
  TOP w0.92: 127.22,47.2 R109.1
SIG106: length 2.5
  TOP w0.3: 129.03,44.9 127.4,44.9
  TOP w0.92: 127.4,44.9 R74.1
  TOP w1.1: D38.C 129.03,44.9
SIG115:
  vias: v5(230.05,65.3) v5(230.05,55.7) v5(230.05,49.7)
SIG116: length 39
  TOP w0.3: v2(232.95,58.6) 232.95,58.05 230.94,56.03 230.94,55.66
  TOP w0.55: IC7.7 230.94,55.66
  CONDUCTIVE4 w0.6: v2(232.95,58.6) 232,57.65 232,46.95 233.5,45.45 233.5,42.95 229.05,38.5 v2(229.05,38.1)
  BOTTOM w0.3: v2(229.05,38.1) 229.05,38.9 228.7,39.25 227.79,39.25 ; 224.83,35.12 225.6,35.12 227.6,37.12 227.6,38.53 ; 224.37,35.12 222.88,35.12 222.3,35.7
  BOTTOM w0.55: 227.6,38.53 D29.C 227.79,39.25
  BOTTOM w0.8: 224.37,35.12 D57.A 224.83,35.12
  BOTTOM w1.1: 222.3,35.7 D58.C
SIG117: length 19.3
  TOP w0.3: v2(228.95,61.55) 227.85,61.55 227.35,61.05 227.35,57.2 228.26,56.29 228.26,55.67
  TOP w0.825: 228.26,55.67 IC7.5
  BOTTOM w0.3: 235.95,65 235.38,64.42 235.38,62.93 ; 234.08,62.7 235.14,62.7 ; v2(228.95,61.55) 229.7,60.8 232.83,60.8 233.55,61.52 233.55,62.51
  BOTTOM w0.55: 234.08,62.7 D28.C 233.55,62.51
  BOTTOM w0.8: 235.14,62.7 D55.A 235.38,62.93
  BOTTOM w1.1: D56.C 235.95,65
SIG118: length 62.2
  TOP w0.3: v2(233.5,46.75) 227.45,46.75 226.85,46.15 226.85,44.2 226.35,43.7 v2(225.65,43.7) ; 233.47,67.39 233.5,67.76 v2(233.5,68.25) ; v2(243.85,63.3) 241.9,63.3
  TOP w0.5: 233.47,67.39 Q27.4
  TOP w2.1: 241.9,63.3 TP20.1
  CONDUCTIVE4 w0.6: v2(233.5,46.75) 233.5,50.05 v2(236.25,52.8) 236.25,53.4 235.75,53.9 234.75,53.9 234.05,54.6 234.05,61.05 235.25,62.25 242.8,62.25 v2(243.85,63.3) 243.85,64.35 242.15,66.05 234.6,66.05 233.5,67.15 v2(233.5,68.25)
  BOTTOM w0.3: R25.2 225.24,43.66 v2(225.65,43.7) ; 224.6,43.49 224.6,42.45 ; v2(233.5,46.75) 233.47,47.16 233.47,47.66 ; v2(236.25,52.8) 236.24,53.21 R219.1 ; 222.87,42.25 224.03,42.25
  BOTTOM w0.5: Q9.4 233.47,47.66
  BOTTOM w0.72: R25.2 224.6,43.49
  BOTTOM w0.92: 224.6,42.45 R24.2 224.03,42.25 ; R215.2 222.87,42.25
SIG121: length 7.7
  TOP w0: C90.2 229.65,49.24 229.51,49.1
  TOP w0.45: 229.65,50.95 229.65,49.69 ; 229.66,54.28 229.66,53.31 229.68,53.3 229.68,52.98 229.65,52.29
  TOP w0.5: 229.51,49.1 228.82,49.06 228.28,49.06
  TOP w0.55: 229.66,55.04 229.66,54.28
  TOP w0.72: R124.2 228.28,49.06
  TOP w0.92: 229.65,49.69 C90.2 ; 229.65,50.95 C91.2 229.65,52.29 ; 229.51,49.1 229.65,49.1
SIG122: length 1.9
  BOTTOM w0.3: 272.19,34.88 272.19,35.63 C59.1
  BOTTOM w0.825: 272.19,34.88 IC8.8
SIG124: length 6.8
  TOP w0.45: 229.65,96.39 229.82,97.06 229.82,97.4 229.89,97.33 IC6.6
  TOP w0.5: 229.65,94.99 229.65,93.11
  TOP w0.92: 229.65,96.39 C88.2 229.65,94.99 ; 229.65,93.11 C89.2
SIG126: length 12.2
  TOP w0.3: v2(233.15,94.95) 233.15,95.3 232.5,95.95 232.49,95.95 232.16,96.06
  TOP w0.55: IC6.7 232.16,96.06
  BOTTOM w0.3: D54.C 231.22,93.08 230.43,92.28 230.43,91.73 ; 229.66,94.7 229.95,94.7 230.2,94.95 v2(233.15,94.95) ; 228.95,94.51 228.95,94.1 229.25,93.8 230.57,93.8
  BOTTOM w0.55: 228.95,94.51 D26.C 229.66,94.7
  BOTTOM w0.8: 230.43,91.73 D53.A
  BOTTOM w1.1: D54.C 230.57,93.8
SIG127: length 22.6
  TOP w0.3: 232.03,98.74 232.81,98.74 233.1,98.45 v2(233.1,96.5)
  TOP w0.825: IC6.5 232.03,98.74
  CONDUCTIVE4 w0.6: v2(233.1,96.5) 231.85,97.75 v2(231.85,105.6)
  BOTTOM w0.3: v2(231.85,105.6) 231.85,106.25 230.38,107.72 230.38,108.33 ; 230.95,110.4 230.43,109.86 230.38,109.8 D51.A ; 229.95,113.01 229.95,111.45 230.27,111.13 230.67,110.4
  BOTTOM w0.55: D27.C 229.95,113.01
  BOTTOM w0.8: 230.38,108.33 D51.A
  BOTTOM w1.1: D52.C 230.67,110.4
SIG128: length 38.7
  TOP w0.3: TP19.1 239.9,112.5 239.7,112.3 v2(233.45,112.3) 233.45,111.16 233.47,110.79 ; v2(233.45,105.6) 233.45,104.63 Q26.4
  TOP w0.5: 233.47,110.79 Q13.4
  CONDUCTIVE4 w0.6: v2(239,92.95) 237.15,94.8 v2(237.15,100) 236.85,100.3 234.9,100.3 233.45,101.75 v2(233.45,105.6) v2(233.45,112.3)
  BOTTOM w0.3: R217.1 v2(237.15,100) ; 238.78,93.86 238.25,93.8 237.56,93.8 ; 237.55,93.16 237.55,91.89 ; R21.2 v2(239,92.95)
  BOTTOM w0.72: 238.78,93.86 R21.2
  BOTTOM w0.92: 237.55,93.16 R213.2 237.56,93.8 ; 237.55,91.89 R20.2
SIG134:
  vias: v5(230.05,108.7) v5(230.05,102.7) v5(230.05,102.7)
SIG135: length 1.8
  TOP w2: TP30.1 219.9,121.6
  vias: v5(230.05,121.4) v5(230.05,121.4) v5(230.05,115.4)
SIG136: length 1.8
  BOTTOM w0.45: 268.1,35.69 268.1,35.15 268.11,34.64
  BOTTOM w0.72: R6.1 268.1,35.69
  BOTTOM w0.825: 268.11,34.64 IC8.5
SIG138: length 54.7
  TOP w0.3: v2(206.5,121.6) TP27.1
  CONDUCTIVE3 w0.2: v2(206.5,121.6) 207.2,120.9 218.7,120.9 222,117.6 242.5,117.6 R128.1
  BOTTOM w2: 234.85,116.6 242.4,116.6 ; 237.05,98.1 243.2,98.1
SIG141: length 83.6
  TOP w0.3: v2(268.1,38.15) 268.1,39.6 268.7,40.2 270.27,40.2 ; 279.6,70.98 v2(279.6,72) ; 286.1,70.98 v2(286.1,72) ; 299.1,70.98 v2(299.1,72) ; 273.1,70.98 v2(273.1,72) ; 292.6,70.98 v2(292.6,72)
  TOP w0.5: Q16.4 292.6,70.98 ; Q19.4 273.1,70.98 ; Q15.4 299.1,70.98 ; Q17.4 286.1,70.98 ; Q18.4 279.6,70.98
  TOP w2.1: 270.27,40.2 TP28.1
  CONDUCTIVE4 w0.2: v2(299.1,72) v2(292.6,72) v2(286.1,72) v2(279.6,72) v2(273.1,72) 271.2,70.11 271.2,61.65 266.65,57.1 266.65,39.6 v2(268.1,38.15)
  BOTTOM w0.3: 272.9,70.98 272.9,71.81 v2(273.1,72) ; v2(292.6,72) 292.4,71.81 292.4,70.98 ; v2(299.1,72) 298.9,71.81 298.9,70.98 ; 279.4,70.98 279.4,71.81 v2(279.6,72) ; v2(286.1,72) 285.9,71.81 285.9,70.98
  BOTTOM w0.45: v2(268.1,38.15) R6.2
  BOTTOM w0.5: 298.9,70.98 Q20.4 ; 272.9,70.98 Q24.4 ; 292.4,70.98 Q21.4 ; 285.9,70.98 Q22.4 ; 279.4,70.98 Q23.4
SIG148: length 7.4
  TOP w0.3: R180.2 254.31,11.45 253.15,11.45 252.7,11.9 v2(252.7,12.2) ; 254.76,11.68 254.76,10.12
  TOP w0.72: R180.2 254.76,11.68 ; 254.76,10.12 R51.2
  BOTTOM w0.3: 254.4,12.82 254.03,12.82 253.93,12.93 253.4,12.93 252.98,12.5 v2(252.7,12.2)
  BOTTOM w0.4: IC10.6 254.4,12.82
SIG149: length 5.4
  TOP w0.3: v2(253.7,12.2) 254.76,13.26 254.76,13.8 ; 254.76,15.58 254.76,14.12
  TOP w0.72: 254.76,14.12 R52.2 254.76,13.8 ; R181.2 254.76,15.58
  BOTTOM w0.3: 254.38,12.18 253.72,12.18 v2(253.7,12.2)
  BOTTOM w0.4: IC10.7 254.38,12.18
SIG150: length 8.9
  TOP w0.3: 254.76,7.78 254.76,6.32 ; v2(252.7,10.8) 252.7,8.9 253.6,8 254.54,8
  TOP w0.72: 254.76,7.78 R53.2 254.54,8 ; 254.76,6.32 R182.2
  BOTTOM w0.3: 254.3,11.53 254,11.53 253.9,11.43 253.32,11.43 v2(252.7,10.8)
  BOTTOM w0.4: IC10.8 254.3,11.53
SIG151: length 4.6
  BOTTOM w0.3: 253.7,7.56 253.7,10.4 254.18,10.88 254.47,10.88
  BOTTOM w0.4: IC10.9 254.47,10.88
  BOTTOM w0.72: 253.7,7.56 R54.2
SIG152: length 38.6
  TOP w0.3: v2(252.7,13.5) 252.7,14.3 253.7,15.3 253.7,16.64 R50.2
  CONDUCTIVE4 w0.2: CN10.1 266.45,14.3 260.45,20.3 251.6,20.3 250.85,19.55 250.85,16.6 252.7,14.75 v2(252.7,13.5)
  BOTTOM w0.3: 254.3,13.47 253.11,13.47 v2(252.7,13.5) ; C25.2 256.31,12.37 256.31,13.03 255.86,13.47 255.66,13.47
  BOTTOM w0.4: 254.3,13.47 IC10.5 255.66,13.47
SIG154: length 4
  BOTTOM w0.3: 255.72,15.43 256.02,15.43 256.76,16.16 257.18,16.16 ; 257.52,16.16 258.06,16.16 258.6,16.2
  BOTTOM w0.4: IC10.2 255.72,15.43
  BOTTOM w0.72: 257.52,16.16 R44.1 257.18,16.16 ; 258.6,16.2 R45.2
SIG156: length 15.2
  BOTTOM w0.3: 259.2,10.9 260.9,10.9 261.44,11.44 R47.2 ; 264.04,13.4 263.5,13.34 262.96,13.34 ; R43.2 261.44,14.06 260.2,15.3 256.75,15.3 256.22,14.78 255.68,14.78 ; 261.58,13.4 262.12,13.4 262.66,13.34 ; 261.44,13.24 261.44,12.16
  BOTTOM w0.4: 255.68,14.78 IC10.3
  BOTTOM w0.45: 259.2,10.9 259.02,10.9
  BOTTOM w0.72: 261.44,13.24 R43.2 261.58,13.4 ; 262.96,13.34 C20.1 262.66,13.34 ; 261.44,12.16 R47.2 ; 264.04,13.4 R42.1
SIG157: length 21.6
  TOP w0.3: v2(278.8,3.5) TP33.1
  BOTTOM w0.3: 265.54,11.96 274,3.5 v2(278.8,3.5) ; 265.54,13.24 265.54,12.16 ; 265.54,13.62 265.54,14.34 R75.1
  BOTTOM w0.72: 265.54,12.16 R46.2 265.54,11.96 ; 265.54,13.62 R42.2 265.54,13.24
SIG167: length 1.3
  BOTTOM w0.3: 259,12.28 259.27,12 R47.1
SIG168: length 34.6
  TOP w0.3: v2(272.1,3.5) TP32.1
  CONDUCTIVE3 w0.2: v2(272.1,3.5) 270.8,4.8 262.8,4.8 259.35,8.25 259.35,10.8 255.95,14.2 v2(253.7,14.2)
  BOTTOM w0.3: v2(253.7,14.2) 254.11,14.12 254.47,14.12 ; C21.2 258.82,13.3 258.14,13.3 257.62,13.16 ; 258.18,11.07 258.2,11.41 258.2,12.36 R48.2 ; 257.18,13.16 256.78,13.52 256.18,14.12 255.79,14.12
  BOTTOM w0.4: 255.79,14.12 IC10.4 254.47,14.12
  BOTTOM w0.45: 258.18,11.07 C22.2
  BOTTOM w0.72: 257.62,13.16 R48.2 257.18,13.16
SIG170: length 1.5
  BOTTOM w0.3: 264.06,12 263.53,12.06 262.99,12.06
  BOTTOM w0.72: C20.2 262.99,12.06 ; 264.06,12 R46.1
SIG171: length 7.1
  TOP w0.3: 248.44,8.1 248.18,8.57 v2(247.45,9.3) 247.04,9.3 246.61,9
  TOP w0.72: 248.44,8.1 R65.1 ; 246.61,9 R209.2
  BOTTOM w0.3: 248.58,9.57 247.72,9.57 v2(247.45,9.3) R66.2 ; 246.54,9.14 246.54,8.06
  BOTTOM w0.4: IC10.14 248.58,9.57
  BOTTOM w0.72: R66.2 246.54,9.14 ; 246.54,8.06 R211.1
SIG172: length 8.6
  TOP w0.3: 248.44,6.2 247.75,6.2 v2(247.45,6.5) 247.14,6.5 R208.2
  TOP w0.72: 248.44,6.2 R63.1
  BOTTOM w0.3: 248.82,8.82 248.12,8.82 247.45,8.15 v2(247.45,6.5) R64.2 ; 246.54,6.34 246.54,5.26
  BOTTOM w0.6: IC10.13 248.82,8.82
  BOTTOM w0.72: R64.2 246.54,6.34 ; 246.54,5.26 R210.1
SIG173: length 9.9
  TOP w0.3: v2(251,9.7) 250.7,10 R70.2 ; 249.94,7.88 249.94,6.42 ; 249.94,9.78 249.94,8.32
  TOP w0.72: R70.2 249.94,9.78 ; 249.94,8.32 R65.2 249.94,7.88 ; 249.94,6.42 R63.2
  BOTTOM w0.3: v2(251,9.7) 250.47,10.22 249.93,10.22 ; 247.59,10.47 247.13,10.47 246.62,10.66 ; 248.75,10.22 247.95,10.22 C26.2
  BOTTOM w0.4: 249.93,10.22 IC10.15 248.75,10.22
  BOTTOM w0.45: C26.2 247.59,10.47
  BOTTOM w0.72: 246.62,10.66 R69.1
SIG174: length 2.8
  BOTTOM w0.3: 246.18,11.94 245.66,12.1 245.1,12.1 ; 245.04,11.94 245.04,10.86
  BOTTOM w0.72: 246.18,11.94 R69.2 ; 245.04,10.86 R67.1 ; 245.1,12.1 R59.2 245.04,11.94
SIG175: length 28.2
  CONDUCTIVE4 w0.2: v2(242.8,12.1) 245,9.9 245,7.55 247.25,5.3 250.2,5.3 251.55,6.65 v2(262.25,6.65)
  BOTTOM w0.3: R62.1 261.84,6.66 v2(262.25,6.65) ; 259.46,6.8 260.46,6.8 260.98,6.66 ; v2(242.8,12.1) 243.75,12.1
  BOTTOM w0.72: 260.98,6.66 R62.1 ; R60.2 259.46,6.8 ; 243.75,12.1 R59.1
SIG177: length 7.8
  TOP w0.3: R184.2 257.47,5.87 v2(257,5.4)
  BOTTOM w0.3: 257.74,6.8 256.3,6.8 255.06,8.04 255.06,8.71 ; R61.2 v2(257,5.4) ; 257.96,6.64 257.96,5.56
  BOTTOM w0.6: IC10.12 255.06,8.71
  BOTTOM w0.72: 257.74,6.8 R60.1 257.96,6.64 ; 257.96,5.56 R61.2
SIG179: length 5.9
  TOP w0.3: 257.96,11.38 257.96,10.22 ; v2(257,9.6) 257.4,10 257.94,10
  TOP w0.72: 257.96,10.22 R55.2 257.94,10 ; R207.1 257.96,11.38
  BOTTOM w0.3: R57.1 v2(257,9.6) 256.38,10.22 255.72,10.22
  BOTTOM w0.4: IC10.10 255.72,10.22
SIG181: length 4.7
  TOP w0.3: v2(257,8.2) 257.2,8 257.74,8
  TOP w0.72: 257.74,8 R58.1
  BOTTOM w0.3: 255.66,9.57 256,9.57 257,8.57 v2(257,8.2) R56.2
  BOTTOM w0.4: IC10.11 255.66,9.57
SIG183: length 4
  BOTTOM w0.3: 246.78,15.57 247.53,15.57 ; 246.47,15.57 246.13,15.57 245.66,15.8 ; 248.72,15.43 248.18,15.43 247.88,15.57
  BOTTOM w0.4: IC10.23 248.72,15.43
  BOTTOM w0.45: 246.78,15.57 C23.2 246.47,15.57 ; 247.88,15.57 C24.2 247.53,15.57
  BOTTOM w0.72: 245.66,15.8 R49.2
SIG185: length 3.2
  TOP w0.4: 201.41,14.79 202.03,14.88 C67.2 203.18,14.88 203.71,15
  TOP w0.72: R117.1 203.71,15
  TOP w0.825: 201.41,14.79 200.78,14.79
SIG193: length 25.2
  BOTTOM w5: F1.1 32.1,58 19.7,45.6 CN1.1
SIG199: length 21.2
  BOTTOM w0: C32.2 77.04,35.11 77.44,35.11 C52.2
  BOTTOM w5: L12.2 86.45,33.25 C52.2 72.15,33.25 L11.1
SIG200: length 34.1
  BOTTOM w5: 70.3,10 70.3,16.8 74.25,20.75 79.2,20.75 ; 79.5,20.75 84.65,20.75 88.4,17 88.4,10.7
SIG205: length 34
  TOP w0.3: 172.45,71.44 172.45,72.98 172.24,73.48 ; 172.24,73.92 172.24,75 170.8,76.44 Q4.G 170.8,82.8 169.85,83.75 157.1,83.75 155.59,85.26 154.75,86.6 ; 172.45,70.23 172.45,69.07
  TOP w0.72: 172.24,73.48 R33.2 172.24,73.92
  TOP w0.92: 172.45,71.44 R135.2 172.45,70.23 ; 172.45,69.07 R134.2
  TOP w2.1: 154.75,86.6 TP12.1
SIG206: length 20.1
  TOP w0.3: R31.2 149.41,74.65 150.31,74.65 ; 151.16,74.65 151.85,74.65 151.9,74.7 R126.2 ; 152.95,75.3 152.95,76.89 153.4,77.34 Q3.G 152.01,81.44 148.32,85.13 147.75,86.6
  TOP w0.92: 151.16,74.65 R127.2 150.31,74.65 ; 152.95,75.3 R126.2
  TOP w2.1: TP11.1 147.75,86.6
SIG223: length 3.2
  TOP w0.4: 201.5,13.7 201.91,13.7 202.45,13.64
  TOP w0.5: 203.84,13.6 203.3,13.6 202.76,13.64
  TOP w0.55: 200.78,13.7 201.5,13.7
  TOP w0.72: 202.76,13.64 C66.2 202.45,13.64 ; R130.2 203.84,13.6
SIG228: length 1.8
  BOTTOM w0.3: R153.2 226.94,8.1 226.94,8.1 227.5,8.3
  BOTTOM w0.8: IC13.5 227.5,8.3
SIG229: length 2.9
  BOTTOM w0.3: 226.24,9.02 226.32,9.55 226.32,9.93 ; 227.5,9.57 226.95,9.8 226.9,9.8 226.6,10.1 226.32,10.1
  BOTTOM w0.45: 226.32,10.1 226.32,9.93
  BOTTOM w0.72: 226.24,9.02 R157.2
  BOTTOM w0.8: IC13.6 227.5,9.57
SIG230: length 35.4
  TOP w0.3: v2(265.4,3.5) TP34.1
  CONDUCTIVE3 w0.2: v2(238.75,10.55) 240.7,8.6 240.7,7.45 244.15,4 245.45,4 246.45,5 252.85,5 253.65,4.2 264.7,4.2 v2(265.4,3.5)
  BOTTOM w0.3: 237.51,9.57 238.12,9.57 238.65,9.6 ; R149.1 238.75,10.14 v2(238.75,10.55)
  BOTTOM w0.72: 238.65,9.6 R149.1
  BOTTOM w0.8: IC13.1 237.51,9.57
SIG231: length 3
  BOTTOM w0.3: 226.24,4.52 226.32,5.05 226.32,5.42 ; 227.5,4.77 227.04,5.16 226.7,5.5 226.38,5.6
  BOTTOM w0.45: 226.32,5.42 226.32,5.6 226.38,5.6
  BOTTOM w0.72: 226.24,4.52 R160.2
  BOTTOM w0.8: IC14.6 227.5,4.77
SIG234: length 1.8
  BOTTOM w0.3: 227.5,3.5 226.84,3.5 R154.2
  BOTTOM w0.8: IC14.5 227.5,3.5
SIG236: length 19.8
  TOP w0.3: v2(252,3.5) TP35.1
  CONDUCTIVE3 w0.2: v2(252,3.5) 251.3,4.2 246.85,4.2 245.85,3.2 241.6,3.2 v2(238.75,6.05)
  BOTTOM w0.3: v2(238.75,6.05) 238.75,5.56 238.76,5.02 ; 238.67,4.8 238.13,4.77 237.53,4.77
  BOTTOM w0.72: 238.67,4.8 R150.1 238.76,5.02
  BOTTOM w0.8: IC14.1 237.53,4.77
SIG237: length 2.8
  TOP w0.3: 226.47,6.53 227,6.53 227.08,6.6 227.5,7.03 ; 226.24,7.5 226.3,6.96 226.3,6.62
  TOP w0.45: 226.47,6.53 C73.2 226.3,6.62
  TOP w0.72: 226.24,7.5 R163.2
  TOP w0.8: IC15.6 227.5,7.03
SIG242: length 1.8
  TOP w0.3: 227.5,8.3 226.95,8.55 226.79,8.55 R155.2
  TOP w0.8: IC15.5 227.5,8.3
SIG243: length 15
  TOP w0.3: v2(247.1,3.5) 247.1,3.08 246.55,1.6 ; 237.53,2.23 238.13,2.23 238.67,2.2 ; v2(238.75,3.5) 238.75,2.96 238.76,2.42
  TOP w0.72: 238.67,2.2 R152.1 238.76,2.42
  TOP w0.8: IC16.1 237.53,2.23
  TOP w2.1: 246.55,1.6 TP37.1
  CONDUCTIVE3 w0.2: v2(247.1,3.5) 246.4,2.8 239.45,2.8 v2(238.75,3.5)
SIG245: length 1.9
  TOP w0.3: R156.2 227.04,3.7 227.05,3.7 227.5,3.5
  TOP w0.8: IC16.5 227.5,3.5
SIG246: length 2.7
  TOP w0.3: 226.3,2.1 226.24,2.43 226.24,3.08 ; 226.47,1.93 226.8,2 226.95,2 227.5,2.23
  TOP w0.45: 226.47,1.93 C74.2 226.3,2.1
  TOP w0.72: R166.2 226.24,3.08
  TOP w0.8: IC16.6 227.5,2.23
SIG247: length 28.2
  TOP w0.3: 238.65,7 238.12,7.03 237.51,7.03 ; v2(238.75,8.3) 238.75,7.76 238.76,7.22 ; v2(258.7,3.5) TP36.1
  TOP w0.72: 238.76,7.22 R151.1 238.65,7
  TOP w0.8: IC15.1 237.51,7.03
  CONDUCTIVE3 w0.2: v2(238.75,8.3) 238.75,7 242.15,3.6 245.65,3.6 246.65,4.6 252.65,4.6 253.75,3.5 v2(258.7,3.5)
SIG249: length 64.2
  TOP w0.3: 148.4,116.95 148.4,116.6 ; 148.4,116.95 Q5.S ; 148.4,116.95 148.75,116.6 ; 148.4,116.95 148.05,116.6 ; 148.4,116.6 148.75,116.6 ; 148.4,116.6 148.05,116.6 ; 148.75,116.6 152.1,116.6 152.75,115.95 152.75,115.37 ; 148.05,116.6 144.16,116.6 143.66,116.8 ; 152.18,105.1 152.76,105.1 153.3,105.64 153.3,105.8 ; 167.05,114.3 172.75,114.3 v2(173.25,113.8) ; 152.94,114.65 153.85,114.65 155.25,113.25 155.25,107.59 153.64,105.97 153.47,105.97
  TOP w0.45: 153.3,105.8 C18.1 153.47,105.97
  TOP w0.55: 152.75,115.37 D23.A 152.94,114.65 ; IC5.11 152.18,105.1
  TOP w0.72: 143.66,116.8 R28.1
  TOP w2.1: 167.05,114.3 TP15.1
  CONDUCTIVE3 w0.6: 165.35,112.9 166.25,113.8 v2(173.25,113.8)
  CONDUCTIVE3 w5: 161.15,100.2 161.15,115.21 158.65,115.21
SIGN254: length 1.8
  TOP w0.3: R172.1 153.9,41.67 154.22,42 154.22,42.51
  TOP w0.55: 154.22,42.51 D30.A
SIGN255: length 1.7
  TOP w0.3: 137.91,43.58 137.5,43.6 136.66,43.6
  TOP w0.55: 137.91,43.58 D32.A
  TOP w0.72: R173.1 136.66,43.6
SIGN256: length 6.7
  TOP w0.3: v2(155.4,2.3) 154.86,2.3 154.32,2.36
  TOP w0.72: 154.32,2.36 R177.1
  BOTTOM w0.3: 156.36,2.84 156.36,1.76 ; 156.32,4.28 156.36,3.83 156.36,3.18 ; R97.1 154.96,1.86 v2(155.4,2.3) 155.74,1.96 156.14,1.6
  BOTTOM w0.6: 156.32,4.28 156.32,4.47
  BOTTOM w0.72: 156.14,1.6 R96.2 156.36,1.76 ; 156.36,2.84 C77.2 156.36,3.18
SIGN260: length 7.7
  BOTTOM w0.3: 162.04,1.7 160.82,1.7 160.32,2.2 ; 156.85,5.22 157.15,5.22 157.9,4.48 158.2,4.2 158.83,4.2 160.32,2.7 160.32,2.36
  BOTTOM w0.4: 156.32,5.22 156.85,5.22
  BOTTOM w0.45: 160.32,2.36 160.32,2.2
  BOTTOM w0.72: 162.04,1.7 R170.2
SIGN262: length 7.4
  BOTTOM w0.3: 157.02,5.88 157.43,5.88 158.4,4.9 159.47,4.9 C75.2 ; 162.04,3.1 160.8,3.1 159.88,4.03 159.88,4.36
  BOTTOM w0.4: 157.02,5.88 156.32,5.88
  BOTTOM w0.45: C75.2 159.88,4.36
  BOTTOM w0.72: 162.04,3.1 R169.2
SIGN266: length 26.3
  TOP w0.3: 159.05,38.5 160.78,38.5 162.6,40.32 162.6,46.65 161.88,47.38 FB1.2 ; Q2.G 153.7,51.15 155.95,48.9 160.1,48.9 160.6,48.4 160.6,47.67
  TOP w1.17: FB1.2 160.6,47.67
  TOP w2.1: 159.05,38.5 TP3.1
SIGN267: length 15.9
  TOP w0.3: 124,61.9 122.5,60.4 Q1.G 122.5,47.67
  TOP w1.17: 122.5,47.67 FB2.2
  TOP w2.1: TP4.1 124,61.9
SIGN269: length 13.2
  TOP w0.3: 150.73,106.37 150.3,106.37 150.1,106.57 150.1,110.21 149.22,111.08 149.22,112.34 ; 148.65,114.7 149.17,114.16 149.22,114.1 149.22,112.63 ; 151.61,112.55 151.22,112.4 149.46,112.4
  TOP w0.55: 151.61,112.55 D23.C ; 150.73,106.37 IC5.12
  TOP w0.8: 149.22,112.63 D42.A ; D42.A 149.46,112.4 ; D42.A 149.22,112.34
  TOP w1.1: D43.C 148.65,114.7
SIGN270: length 10.3
  TOP w0.3: IC5.7 146.53,100.54 146.53,100.08 ; 148.24,99.05 148.24,99.7 148.04,99.9 146.7,99.9
  TOP w0.45: 146.53,100.08 C55.2 ; C55.2 146.53,99.58 146.55,98.89 ; C55.2 146.7,99.9 ; 146.6,94.28 146.55,94.82 146.55,95.51 ; 146.55,97.55 146.55,96.29
  TOP w0.72: 146.6,94.28 R123.2
  TOP w0.895: 148.24,99.05 R114.1
  TOP w0.92: 146.55,96.29 C86.2 146.55,95.51 ; 146.55,98.89 C87.2 146.55,97.55
SIGN271: length 4.4
  BOTTOM w0: R178.1 180.7,14.7 180.69,14.7 R179.2
SIGN273: length 51.7
  BOTTOM w0.15: 233.35,66.7 D35.C ; 233.55,66.9 233.9,67.25 R105.2 ; C51.2 241.2,67 241.3,66.9
  BOTTOM w1.5: 233.35,66.7 233.55,66.9 246.6,66.9 R107.1 247.4,50.7 238.2,41.5 236.72,41.5
SIGN275: length 3
  TOP w0.3: 85.3,77.74 86.71,77.74 87.3,77.15 87.3,76.83
  TOP w0.4: 87.3,76.83 D48.A
  TOP w0.7: D50.A 85.3,77.74
SIGN284: length 1.5
  BOTTOM w0.3: 238.67,7 238.13,7.03 237.53,7.03
  BOTTOM w0.72: 238.67,7 R194.1
  BOTTOM w0.8: IC13.3 237.53,7.03
SIGN287: length 1.5
  BOTTOM w0.3: 237.5,2.23 238.1,2.23 238.64,2.2
  BOTTOM w0.72: 238.64,2.2 R195.1
  BOTTOM w0.8: IC14.3 237.5,2.23
SIGN289: length 1.5
  TOP w0.3: 238.65,4.8 238.12,4.77 237.51,4.77
  TOP w0.72: 238.65,4.8 R197.1
  TOP w0.8: IC16.3 237.51,4.77
SIGN291: length 1.5
  TOP w0.3: 237.65,9.57 238.25,9.57 R196.1
  TOP w0.8: IC15.3 237.65,9.57
SIGN304: length 2.9
  BOTTOM w0.3: 224.95,7.4 224.29,7.4 223.82,7.66 ; 223.39,7.66 222.87,7.8 222.57,7.8
  BOTTOM w0.4: IC21.2 222.57,7.8
  BOTTOM w0.72: R153.1 224.95,7.4 ; 223.82,7.66 R186.1 223.39,7.66
SIGN305: length 3
  BOTTOM w0.3: 223.76,2.86 224.3,2.9 224.84,2.9 ; 222.41,3.5 222.65,3.5 223.1,3.05 223.6,2.86
  BOTTOM w0.4: IC22.2 222.41,3.5
  BOTTOM w0.72: 223.76,2.86 R188.1 223.6,2.86 ; R154.1 224.84,2.9
SIGN314: length 3.9
  TOP w0.3: R155.1 223.9,9.1 223.5,8.7 223.5,8.16 ; 222.35,7.6 223,7.6 223.01,7.61 223.43,7.94
  TOP w0.4: IC23.2 222.35,7.6
  TOP w0.72: 223.5,8.16 R190.1 223.43,7.94
SIGN315: length 3.3
  TOP w0.3: 223.53,4.14 223.08,3.83 222.65,3.4 222.35,3.4 ; 223.82,4.14 224.22,4.5 R156.1
  TOP w0.4: 222.35,3.4 IC24.2
  TOP w0.72: 223.53,4.14 R192.1 223.82,4.14
SIGN316: length 4.2
  TOP w0.3: 155.9,74.7 157.1,74.7 158.01,73.79 158.7,73.33
  TOP w0.92: 155.9,74.7 R126.1
  TOP w1.1: D40.C 158.7,73.33
SIGN317: length 2.5
  TOP w0.3: 151.09,71.95 151.8,71.95 152.25,72.4 152.85,72.4
  TOP w0.8: 152.85,72.4 D41.A
  TOP w0.92: R127.1 151.09,71.95
SIGN318: length 15.8
  TOP w0.15: IC4.12 158.83,68.55
  TOP w0.3: 155.35,72.4 156.23,72.4 157.96,70.67 158.56,70.67 ; 158.7,70.44 158.83,69.86 158.83,69.37 ; 147.79,68.75 149.45,68.75 151.93,71.23 153.47,71.23 154.64,72.4 D41.C
  TOP w0.55: D24.C 147.79,68.75 ; 158.83,68.55 158.83,69.37
  TOP w0.8: 158.7,70.44 D40.A 158.56,70.67
  TOP w1.1: D41.C 155.35,72.4
SIGN319: length 2.5
  TOP w0.3: 145,112.6 145.66,112.4 146.85,112.4
  TOP w0.92: 145,112.6 R132.1
  TOP w1.1: D42.C 146.85,112.4
SIGN320: length 1.6
  TOP w0.3: 146.21,114.7 145.61,114.7 144.96,114.9
  TOP w0.8: D43.A 146.21,114.7
  TOP w0.92: 144.96,114.9 R133.1
SIGN321: length 19.6
  TOP w0.3: 141.94,116.8 139.38,116.8 137.5,118.67 Q5.G 134.3,121.8 133.75,121.25 132.95,119.9 ; 142.05,115.3 142.05,116.05 142.16,116.58 ; 142.05,114.26 142.05,112.99
  TOP w0.72: 141.94,116.8 R28.2 142.16,116.58
  TOP w0.92: 142.05,114.26 R133.2 142.05,115.3 ; 142.05,112.99 R132.2
  TOP w2.1: 132.95,119.9 TP13.1
